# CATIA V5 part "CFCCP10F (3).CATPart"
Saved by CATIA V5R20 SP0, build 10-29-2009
Part number: CFCCP10F (3)
Revision: TUTTO
Definition: NON CONOSCIUTO
Nomenclature: CFCCP10F (3)
Source: Unknown
Bounding box of the stored display mesh (mm): x -50 to 50, y -29 to 29, z -40 to 0
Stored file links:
  C:\Users\Utente\Desktop\IO LAVORO\3D X SITO CF\X 3D SITO CF 27-09-2020\CFCCP\CFCCP10F\CFCCP10F (3).CATPart
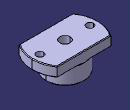
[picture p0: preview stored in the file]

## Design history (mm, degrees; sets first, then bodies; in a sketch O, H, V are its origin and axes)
Body1 "Foro Ø11.0 (11)-1" (main body)
  Solid1: solid without history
